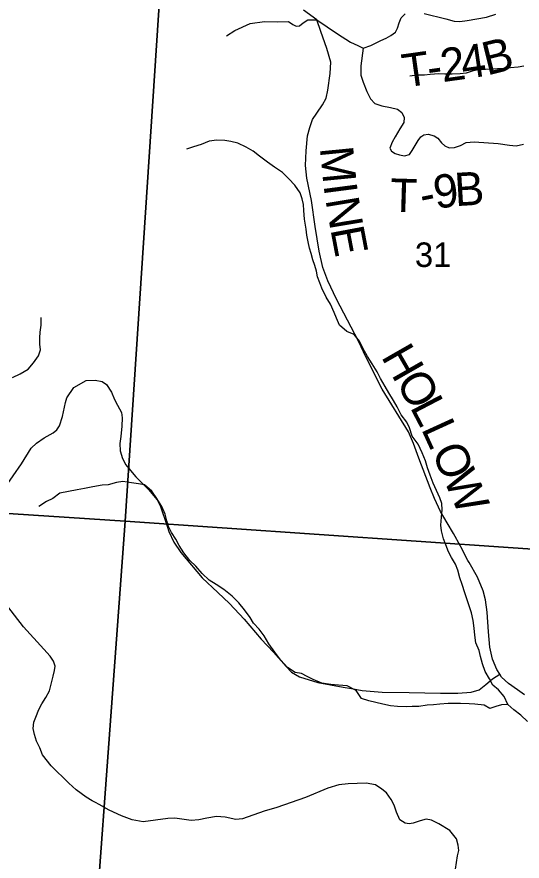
# Model space of a CAD drawing. Extents: x 0 to 34, y 0 to 22.
# Drawn here: x 26.642 to 27.504, y 18.393 to 19.835 of the extents above; entities that cross this region are included whole.
import ezdxf

# ---------------------------------------------------------------- set-up
doc = ezdxf.new("R2010")
doc.units = 0
for name, color, linetype in [('GM_X_County_Road', 7, 'Continuous'), ('GM_X_County_Road_Text', 7, 'Continuous'), ('GM_X_Minor_River', 7, 'Continuous'), ('GM_X_Section', 7, 'Continuous'), ('GM_X_Section_Text', 7, 'Continuous'), ('GM_X_Township_Road', 7, 'Continuous'), ('GM_X_Township_Road_Text', 7, 'Continuous')]:
    doc.layers.add(name, color=color, linetype=linetype)

msp = doc.modelspace()

# ---------------------------------------------------------------- linework, layer by layer
at = {"layer": 'GM_X_County_Road'}
for points in [[(27.414, 18.9026), (27.412, 18.9062), (27.3998, 18.9295), (27.3991, 18.9306), (27.3872, 18.9524), (27.3765, 18.9708), (27.3655, 18.99), (27.3551, 19.0121), (27.3478, 19.0301), (27.3282, 19.0812), (27.319, 19.1063), (27.3107, 19.1259), (27.2655, 19.1987), (27.2386, 19.2528), (27.2251, 19.2806), (27.1878, 19.3528), (27.1728, 19.3837), (27.1642, 19.4067), (27.1581, 19.4346), (27.1514, 19.4767), (27.1453, 19.521), (27.1373, 19.5593), (27.1349, 19.581), (27.1361, 19.6058), (27.1381, 19.6316), (27.1425, 19.6456), (27.1468, 19.6596), (27.1541, 19.6704), (27.1637, 19.6847), (27.1704, 19.6957), (27.1731, 19.7098), (27.1771, 19.7382), (27.178, 19.7572), (27.171, 19.7807), (27.1612, 19.8101), (27.1544, 19.8297), (27.1312, 19.8465)], [(27.5083, 18.6765), (27.4967, 18.6851), (27.4811, 18.6958), (27.4695, 18.7071), (27.4666, 18.7118), (27.4615, 18.72), (27.4539, 18.7377), (27.4496, 18.7582), (27.4472, 18.7842), (27.4447, 18.8178), (27.442, 18.8392), (27.438, 18.8545), (27.4282, 18.8775), (27.414, 18.9026)]]:
    msp.add_lwpolyline(points, dxfattribs=at)
at = {"layer": 'GM_X_Minor_River'}
for points in [[(27.5077, 19.7504), (27.4975, 19.7489), (27.4846, 19.7477), (27.4736, 19.7469), (27.4627, 19.7458), (27.4524, 19.7454), (27.4418, 19.745), (27.4316, 19.7449), (27.4195, 19.7423), (27.4089, 19.7384), (27.3987, 19.7373), (27.3851, 19.7369), (27.3726, 19.7368), (27.3624, 19.7376), (27.3476, 19.7364), (27.3378, 19.7352), (27.3253, 19.7352), (27.3128, 19.7333)], [(27.298, 19.1551), (27.2911, 19.1688), (27.285, 19.1794), (27.277, 19.1926), (27.271, 19.2036), (27.263, 19.2168), (27.2569, 19.2282), (27.2485, 19.2422), (27.2405, 19.2547), (27.2325, 19.2687), (27.2268, 19.2808), (27.2181, 19.2925), (27.2055, 19.2971), (27.1926, 19.308), (27.1877, 19.3201), (27.1839, 19.33), (27.1774, 19.344), (27.1702, 19.3561), (27.1629, 19.3713), (27.1595, 19.3807), (27.1553, 19.3906), (27.1534, 19.4004), (27.1507, 19.4099), (27.1472, 19.4197), (27.1446, 19.4304), (27.1419, 19.4398), (27.1392, 19.4504), (27.1369, 19.4622), (27.1361, 19.472), (27.133, 19.4895), (27.1322, 19.5042), (27.1314, 19.5141), (27.1291, 19.5239), (27.1257, 19.5342), (27.1165, 19.5474), (27.1067, 19.558), (27.0957, 19.569), (27.082, 19.578), (27.0699, 19.5867), (27.0562, 19.5969), (27.0456, 19.6052), (27.0338, 19.612), (27.0194, 19.6188), (27.0073, 19.6222), (26.9971, 19.6237), (26.9834, 19.6244), (26.9706, 19.6225), (26.957, 19.6168), (26.9437, 19.613), (26.9316, 19.6091)], [(26.6346, 19.2187), (26.6482, 19.2248), (26.6614, 19.2332), (26.6708, 19.2438), (26.6795, 19.256), (26.6829, 19.2662), (26.6817, 19.2757), (26.6817, 19.2863), (26.682, 19.2961), (26.6835, 19.3083), (26.6838, 19.3212)], [(27.5139, 18.6313), (27.5025, 18.6419), (27.4904, 18.651), (27.4801, 18.6604), (27.4737, 18.6741), (27.4642, 18.6854), (27.4547, 18.6934), (27.449, 18.7043), (27.4414, 18.7168), (27.4368, 18.7297), (27.4337, 18.7422), (27.4314, 18.7524), (27.4253, 18.7653), (27.4237, 18.7786), (27.4229, 18.7907), (27.421, 18.8036), (27.4179, 18.8169), (27.4145, 18.8271), (27.4065, 18.851), (27.4023, 18.865), (27.3984, 18.8763), (27.3946, 18.8896), (27.3908, 18.8998), (27.3839, 18.9112), (27.379, 18.921), (27.3744, 18.9332), (27.3706, 18.943), (27.3668, 18.9566), (27.3656, 18.9665), (27.3667, 18.9801), (27.3682, 18.993), (27.3674, 19.0033), (27.3639, 19.0135), (27.3582, 19.026), (27.3525, 19.0381), (27.3475, 19.0518), (27.3433, 19.0646), (27.3399, 19.0764), (27.3338, 19.09), (27.3273, 19.1048), (27.317, 19.1184), (27.3121, 19.1328), (27.3075, 19.1426), (27.298, 19.1551)], [(27.4801, 18.6604), (27.4695, 18.6596), (27.4597, 18.657), (27.4495, 18.6535), (27.4396, 18.6588), (27.4241, 18.661), (27.4139, 18.6614), (27.3991, 18.6621), (27.3882, 18.6621), (27.3783, 18.6617), (27.3639, 18.6605), (27.3533, 18.6594), (27.3427, 18.6593), (27.3284, 18.657), (27.3166, 18.657), (27.3064, 18.6562), (27.292, 18.6569), (27.2799, 18.6577), (27.267, 18.661), (27.2549, 18.6637), (27.2428, 18.6667), (27.2307, 18.6704), (27.2211, 18.6844), (27.206, 18.692), (27.1912, 18.6931), (27.1783, 18.6946), (27.1628, 18.6964), (27.1477, 18.7028), (27.1378, 18.7081), (27.1283, 18.7134), (27.117, 18.7149), (27.1041, 18.7232), (27.0927, 18.7361), (27.0824, 18.7497), (27.0725, 18.7637), (27.0641, 18.7777), (27.0558, 18.789), (27.0463, 18.7993), (27.0406, 18.8091), (27.0307, 18.822), (27.0212, 18.8337), (27.0098, 18.845), (26.9954, 18.8564), (26.9825, 18.8651), (26.9707, 18.8726), (26.9586, 18.884), (26.9475, 18.8965), (26.9373, 18.9063), (26.9274, 18.9195), (26.919, 18.9316), (26.9137, 18.9426), (26.9061, 18.954), (26.9008, 18.9642), (26.8985, 18.9737), (26.8954, 18.9854), (26.8897, 18.9987), (26.8809, 19.0119), (26.8726, 19.0244), (26.86, 19.0354), (26.8498, 19.0373), (26.8381, 19.0391), (26.8229, 19.041), (26.8123, 19.0394), (26.7983, 19.0352), (26.7877, 19.0348), (26.7718, 19.0321), (26.7575, 19.0291), (26.745, 19.0268), (26.7302, 19.0241), (26.7158, 19.021), (26.7038, 19.0122), (26.6928, 19.0069), (26.68, 18.9985)]]:
    msp.add_lwpolyline(points, dxfattribs=at)
at = {"layer": 'GM_X_Section'}
for points in [[(25.8788, 20.042), (26.893, 19.9764), (26.8274, 18.9732), (25.8109, 19.0399)], [(27.875, 19.9199), (27.8204, 18.905), (26.8274, 18.9732), (26.893, 19.9764)], [(25.7909, 19.041), (25.8109, 19.0399), (26.8274, 18.9732), (26.7513, 17.9427), (25.7287, 17.9991)], [(26.8274, 18.9732), (27.8204, 18.905), (27.7492, 17.8771), (26.7513, 17.9427)]]:
    msp.add_lwpolyline(points, close=True, dxfattribs=at)
at = {"layer": 'GM_X_Township_Road'}
for points in [[(27, 19.8026), (27.0141, 19.8115), (27.0402, 19.8234), (27.065, 19.8271), (27.0865, 19.8265), (27.1056, 19.8268), (27.1132, 19.8217), (27.1188, 19.8188), (27.1246, 19.8194), (27.1311, 19.8247), (27.1387, 19.8299), (27.1544, 19.8297)], [(27.1544, 19.8297), (27.1893, 19.8058), (27.2116, 19.7914), (27.2239, 19.7859), (27.2331, 19.7813), (27.2294, 19.7511), (27.2294, 19.7352), (27.2334, 19.7235), (27.2398, 19.7076), (27.2456, 19.6948), (27.2529, 19.6868), (27.2649, 19.6829), (27.2799, 19.6801), (27.2921, 19.6773), (27.2994, 19.6715), (27.3031, 19.663), (27.3028, 19.6544), (27.2961, 19.6434), (27.2881, 19.6299), (27.2826, 19.6208), (27.2789, 19.6104), (27.2817, 19.6052), (27.2878, 19.6015), (27.2951, 19.599), (27.3037, 19.5975), (27.3126, 19.5997), (27.3171, 19.6065), (27.322, 19.6152), (27.327, 19.6238), (27.3315, 19.6299), (27.3367, 19.6333), (27.3444, 19.6345), (27.3542, 19.6315), (27.3606, 19.6278), (27.367, 19.6195), (27.3728, 19.6146), (27.3799, 19.611), (27.389, 19.6119), (27.3991, 19.6153), (27.4089, 19.6205), (27.4224, 19.6214), (27.4637, 19.6183), (27.4827, 19.6156), (27.4943, 19.6146), (27.5071, 19.6171)], [(27.2331, 19.7813), (27.2462, 19.7862), (27.2636, 19.7942), (27.2725, 19.7985), (27.2805, 19.8028), (27.2884, 19.8089), (27.2921, 19.8153), (27.2948, 19.8248), (27.2979, 19.833), (27.3052, 19.8398)], [(27.3371, 19.8407), (27.3741, 19.8312), (27.3887, 19.8272), (27.3985, 19.8269), (27.4108, 19.8284), (27.4273, 19.8312), (27.4438, 19.8343), (27.4597, 19.8392)], [(26.622, 19.0304), (26.6503, 19.0713), (26.6669, 19.0978), (26.6757, 19.1065), (26.6887, 19.1157), (26.7044, 19.1242), (26.7104, 19.1292), (26.7152, 19.1364), (26.7203, 19.1523), (26.7255, 19.1758), (26.7275, 19.1839), (26.7394, 19.2019), (26.7607, 19.2138), (26.776, 19.2142), (26.788, 19.2119), (26.7953, 19.2066), (26.8037, 19.1935), (26.8092, 19.1812), (26.8141, 19.1714), (26.8206, 19.1592), (26.8218, 19.1499), (26.8215, 19.1359), (26.8195, 19.118), (26.8182, 19.1061), (26.8186, 19.0937), (26.8191, 19.0919), (26.822, 19.0823), (26.8276, 19.0704), (26.8455, 19.0493), (26.8668, 19.0273), (26.8817, 19.0096), (26.8868, 19.0001), (26.8988, 18.9648), (26.9019, 18.9557), (26.9102, 18.9373), (26.9223, 18.92), (26.9586, 18.8765), (26.9851, 18.8516), (27.0051, 18.833), (27.0302, 18.8058), (27.0594, 18.7719), (27.08, 18.7497), (27.102, 18.725), (27.1112, 18.7152), (27.1249, 18.7072), (27.1559, 18.6979), (27.1994, 18.69), (27.2132, 18.6875)], [(26.9663, 18.4661), (26.9528, 18.4632), (26.9395, 18.4623), (26.9277, 18.4638), (26.9116, 18.4658), (26.9, 18.4653), (26.858, 18.4598), (26.839, 18.4634), (26.8208, 18.47), (26.8001, 18.4799), (26.7826, 18.4896), (26.7765, 18.4928), (26.7709, 18.4957), (26.7608, 18.5021), (26.7435, 18.5145), (26.7312, 18.5257), (26.7006, 18.5557), (26.6862, 18.5741), (26.6814, 18.5859), (26.6759, 18.5973), (26.6723, 18.6089), (26.6704, 18.6191), (26.6714, 18.6303), (26.6744, 18.6384), (26.6797, 18.6514), (26.6852, 18.6611), (26.6917, 18.6721), (26.698, 18.6838), (26.704, 18.7085), (26.7065, 18.7184), (26.7074, 18.7258), (26.7046, 18.734), (26.6993, 18.7427), (26.6883, 18.7547), (26.6539, 18.7931), (26.6068, 18.8527)], [(27.2132, 18.6875), (27.2315, 18.6842), (27.2658, 18.6813), (27.312, 18.6806), (27.365, 18.6795), (27.3949, 18.6793), (27.4177, 18.681), (27.4314, 18.6855), (27.4426, 18.6941), (27.4539, 18.7039), (27.4666, 18.7118)], [(27.3497, 18.4624), (27.3408, 18.4642), (27.3307, 18.4617), (27.3188, 18.4577), (27.3115, 18.4564), (27.3049, 18.4573), (27.2961, 18.4634), (27.2901, 18.4761), (27.2859, 18.4885), (27.2811, 18.498), (27.2732, 18.5095), (27.2654, 18.5158), (27.2544, 18.5228), (27.2382, 18.5259), (27.2076, 18.5245), (27.1915, 18.523), (27.1727, 18.5173), (27.1351, 18.5014), (27.0861, 18.4843), (27.0641, 18.4778), (27.0274, 18.4651), (27.016, 18.464), (26.9976, 18.4676), (26.9832, 18.4689), (26.9663, 18.4661)], [(27.3911, 18.3787), (27.3945, 18.4015), (27.3964, 18.411), (27.3953, 18.4199), (27.3926, 18.4305), (27.381, 18.445), (27.3626, 18.4566), (27.351, 18.4621), (27.3497, 18.4624)]]:
    msp.add_lwpolyline(points, dxfattribs=at)

# ---------------------------------------------------------------- texts
at = {"layer": 'GM_X_County_Road_Text'}
for s, rotation, p in [('M', 275.6268, (27.1592, 19.6113)), ('I', 277.4871, (27.1654, 19.5479)), ('N', 279.4602, (27.1688, 19.5227)), ('E', 280.7354, (27.1772, 19.4721)), ('H', 299.8741, (27.263, 19.2545)), ('O', 299.763, (27.2879, 19.2112)), ('L', 297.6096, (27.3124, 19.1683)), ('L', 294.5944, (27.3317, 19.1313)), ('O', 293.0489, (27.3493, 19.0931)), ('W', 293.7523, (27.3692, 19.0464))]:
    msp.add_text(s, height=0.0568, rotation=rotation, dxfattribs=at).set_placement(p)
at = {"layer": 'GM_X_Section_Text'}
msp.add_text('31', height=0.04186, rotation=0, dxfattribs=at).set_placement((27.3215, 19.4076))
at = {"layer": 'GM_X_Township_Road_Text'}
for s, rotation, p in [('4', 8.2578, (27.4039, 19.7282)), ('B', 13.874, (27.4445, 19.7344)), ('T', 8.001, (27.3038, 19.714)), ('2', 8.0642, (27.369, 19.7232)), ('-', 8.0129, (27.3459, 19.72)), ('B', 3.3509, (27.3906, 19.5114)), ('T', 358.307, (27.2784, 19.5022)), ('9', 7.6995, (27.3571, 19.5068)), ('-', 11.651, (27.3352, 19.5022))]:
    msp.add_text(s, height=0.0568, rotation=rotation, dxfattribs=at).set_placement(p)

doc.saveas('drawing.dxf')
